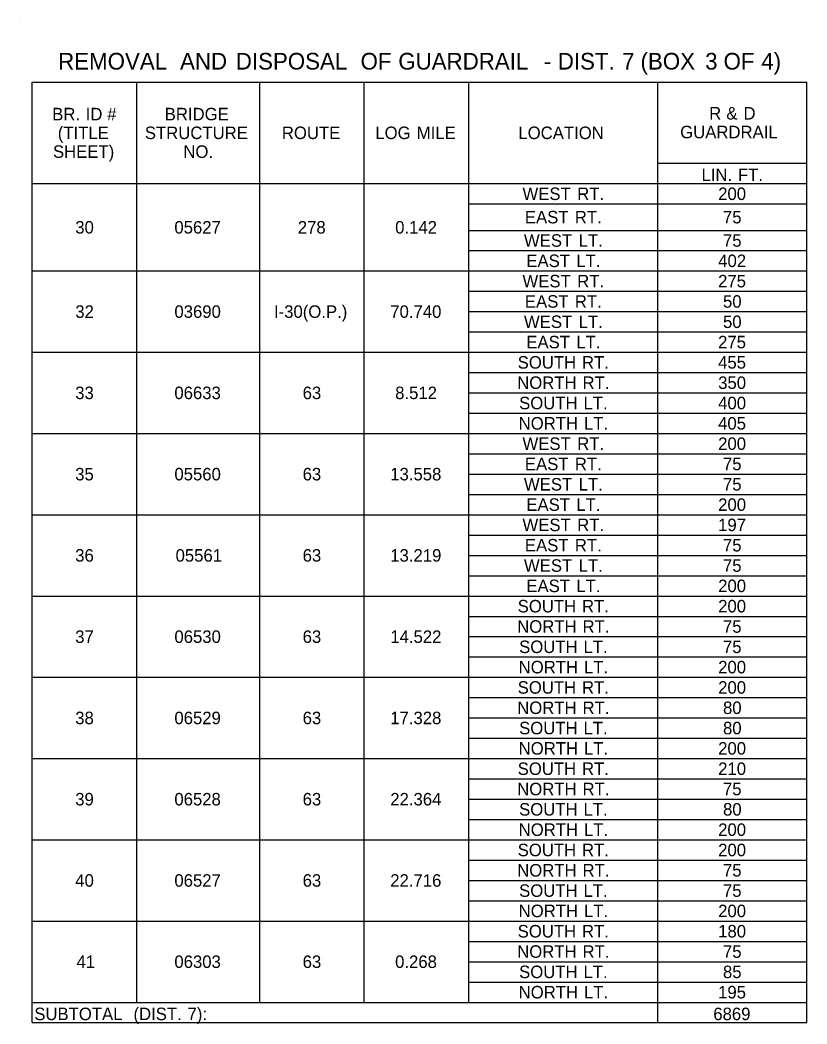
# Model space of a CAD drawing. Extents: x 544250 to 1930787, y -1948365 to 596640.
# Drawn here: x 546903.6 to 547281.5, y -1946709.2 to -1946227.5 of the extents above; entities that cross this region are included whole.
import ezdxf

# ---------------------------------------------------------------- set-up
doc = ezdxf.new("R2010")
doc.units = 0
doc.layers.add('Default', color=7, linetype='Continuous')

msp = doc.modelspace()

# ---------------------------------------------------------------- linework, layer by layer
at = {"layer": 'Default'}
for p, q in [((546903.64, -1946227.46), (546903.64, -1946227.46)), ((546909.49, -1946257.19), (547281.45, -1946257.19)), ((546909.49, -1946708.62), (546909.49, -1946257.19)), ((546909.49, -1946708.62), (546909.49, -1946257.19)), ((546959.7, -1946698.87), (546959.7, -1946257.19)), ((547018.69, -1946698.87), (547018.69, -1946257.19)), ((547068.9, -1946698.87), (547068.9, -1946257.19)), ((547119.11, -1946698.87), (547119.11, -1946257.19)), ((547209.79, -1946708.62), (547209.79, -1946257.19)), ((547281.45, -1946708.62), (547281.45, -1946257.19)), ((547281.45, -1946708.62), (547281.45, -1946257.19)), ((547209.79, -1946296.19), (547281.45, -1946296.19)), ((546909.49, -1946305.94), (547281.45, -1946305.94)), ((546909.49, -1946305.94), (547281.45, -1946305.94)), ((547119.11, -1946315.69), (547281.45, -1946315.69)), ((547119.11, -1946328.37), (547281.45, -1946328.37)), ((547119.11, -1946338.12), (547281.45, -1946338.12)), ((546909.49, -1946347.87), (547281.45, -1946347.87)), ((547119.11, -1946357.62), (547281.45, -1946357.62)), ((547119.11, -1946367.37), (547281.45, -1946367.37)), ((547119.11, -1946377.12), (547281.45, -1946377.12)), ((546909.49, -1946386.87), (547281.45, -1946386.87)), ((547119.11, -1946396.62), (547281.45, -1946396.62)), ((547119.11, -1946406.37), (547281.45, -1946406.37)), ((547119.11, -1946416.12), (547281.45, -1946416.12)), ((546909.49, -1946425.87), (547281.45, -1946425.87)), ((547119.11, -1946435.62), (547281.45, -1946435.62)), ((547119.11, -1946445.37), (547281.45, -1946445.37)), ((547119.11, -1946455.12), (547281.45, -1946455.12)), ((546909.49, -1946464.87), (547281.45, -1946464.87)), ((547119.11, -1946474.62), (547281.45, -1946474.62)), ((547119.11, -1946484.37), (547281.45, -1946484.37)), ((547119.11, -1946494.12), (547281.45, -1946494.12)), ((546909.49, -1946503.87), (547281.45, -1946503.87)), ((547119.11, -1946513.62), (547281.45, -1946513.62)), ((547119.11, -1946523.37), (547281.45, -1946523.37)), ((547119.11, -1946533.12), (547281.45, -1946533.12)), ((546909.49, -1946542.87), (547281.45, -1946542.87)), ((547119.11, -1946552.62), (547281.45, -1946552.62)), ((547119.11, -1946562.37), (547281.45, -1946562.37)), ((547119.11, -1946572.12), (547281.45, -1946572.12)), ((546909.49, -1946581.87), (547281.45, -1946581.87)), ((547119.11, -1946591.62), (547281.45, -1946591.62)), ((547119.11, -1946601.37), (547281.45, -1946601.37)), ((547119.11, -1946611.12), (547281.45, -1946611.12)), ((546909.49, -1946620.87), (547281.45, -1946620.87)), ((547119.11, -1946630.62), (547281.45, -1946630.62)), ((547119.11, -1946640.37), (547281.45, -1946640.37)), ((547119.11, -1946650.12), (547281.45, -1946650.12)), ((546909.49, -1946659.87), (547281.45, -1946659.87)), ((547119.11, -1946669.62), (547281.45, -1946669.62)), ((547119.11, -1946679.37), (547281.45, -1946679.37)), ((547119.11, -1946689.12), (547281.45, -1946689.12)), ((546909.49, -1946698.87), (547281.45, -1946698.87)), ((547209.79, -1946708.62), (547209.79, -1946698.87)), ((546909.49, -1946708.62), (547281.45, -1946708.62))]:
    msp.add_line(p, q, dxfattribs=at)

# ---------------------------------------------------------------- texts
for s, height, p in [('REMOVAL', 8, (546921.92, -1946251.2)), (' AND', 8, (546977.48, -1946251.2)), (' DISPOSAL', 8, (547004.25, -1946251.2)), (' OF', 8, (547064.16, -1946251.2)), (' GUARDRAIL', 8, (547082.27, -1946251.2)), (' DIST.', 8, (547158.85, -1946251.2)), (' 7', 8, (547189.76, -1946251.2)), (' (BOX', 8, (547198.58, -1946251.2)), (' 3', 8, (547229.62, -1946251.2)), (' OF', 8, (547238.45, -1946251.2)), (' 4)', 8, (547256.56, -1946251.2)), (' -', 8, (547152.11, -1946251.2)), ('BR.', 6, (546919.07, -1946275.57)), (' ID', 6, (546932.93, -1946275.57)), (' #', 6, (546943.23, -1946275.57)), ('BRIDGE', 6, (546973.1, -1946275.57)), ('R', 6, (547234.51, -1946275.19)), (' &', 6, (547240.52, -1946275.19)), (' D', 6, (547248.77, -1946275.19)), ('(TITLE', 6, (546921.76, -1946284.57)), ('STRUCTURE', 6, (546963.55, -1946284.57)), ('ROUTE', 6, (547029.33, -1946284.57)), ('LOG', 6, (547074.21, -1946284.57)), (' MILE', 6, (547091.87, -1946284.57)), ('LOCATION', 6, (547142.9, -1946284.57)), ('GUARDRAIL', 6, (547220.59, -1946284.19)), ('SHEET)', 6, (546919.44, -1946293.57)), ('NO.', 6, (546982.03, -1946293.57)), ('LIN.', 6, (547230.83, -1946304.74)), (' FT.', 6, (547246.09, -1946304.74)), ('WEST', 6, (547144.87, -1946313.82)), (' RT.', 6, (547168.93, -1946313.82)), ('200', 6, (547238.83, -1946313.82)), ('EAST', 6, (547146.03, -1946325.03)), (' RT.', 6, (547167.77, -1946325.03)), ('75', 6, (547241.13, -1946325.03)), ('30', 6, (546930.14, -1946329.91)), ('05627', 6, (546977.73, -1946329.91)), ('278', 6, (547036.99, -1946329.91)), ('0.142', 6, (547083.74, -1946329.91)), ('WEST', 6, (547145.57, -1946336.24)), (' LT.', 6, (547169.62, -1946336.24)), ('75', 6, (547241.13, -1946336.24)), ('EAST', 6, (547146.73, -1946345.99)), (' LT.', 6, (547168.46, -1946345.99)), ('402', 6, (547238.85, -1946345.99)), ('WEST', 6, (547144.87, -1946355.74)), (' RT.', 6, (547168.93, -1946355.74)), ('275', 6, (547238.8, -1946355.74)), ('EAST', 6, (547146.03, -1946365.49)), (' RT.', 6, (547167.77, -1946365.49)), ('50', 6, (547241.16, -1946365.49)), ('32', 6, (546930.16, -1946370.37)), ('03690', 6, (546977.74, -1946370.37)), ('I-30(O.P.)', 6, (547025.55, -1946370.37)), ('70.740', 6, (547081.39, -1946370.37)), ('WEST', 6, (547145.57, -1946375.24)), (' LT.', 6, (547169.62, -1946375.24)), ('50', 6, (547241.16, -1946375.24)), ('EAST', 6, (547146.73, -1946384.99)), (' LT.', 6, (547168.46, -1946384.99)), ('275', 6, (547238.8, -1946384.99)), ('SOUTH', 6, (547142.57, -1946394.74)), (' RT.', 6, (547171.23, -1946394.74)), ('455', 6, (547238.8, -1946394.74)), ('NORTH', 6, (547142.33, -1946404.49)), (' RT.', 6, (547171.47, -1946404.49)), ('350', 6, (547238.83, -1946404.49)), ('33', 6, (546930.12, -1946409.37)), ('06633', 6, (546977.73, -1946409.37)), ('63', 6, (547039.32, -1946409.37)), ('8.512', 6, (547083.74, -1946409.37)), ('SOUTH', 6, (547143.26, -1946414.24)), (' LT.', 6, (547171.93, -1946414.24)), ('400', 6, (547238.83, -1946414.24)), ('NORTH', 6, (547143.03, -1946423.99)), (' LT.', 6, (547172.16, -1946423.99)), ('405', 6, (547238.8, -1946423.99)), ('WEST', 6, (547144.87, -1946433.74)), (' RT.', 6, (547168.93, -1946433.74)), ('200', 6, (547238.83, -1946433.74)), ('EAST', 6, (547146.03, -1946443.49)), (' RT.', 6, (547167.77, -1946443.49)), ('75', 6, (547241.13, -1946443.49)), ('35', 6, (546930.1, -1946448.37)), ('05560', 6, (546977.74, -1946448.37)), ('63', 6, (547039.32, -1946448.37)), ('13.558', 6, (547081.38, -1946448.37)), ('WEST', 6, (547145.57, -1946453.24)), (' LT.', 6, (547169.62, -1946453.24)), ('75', 6, (547241.13, -1946453.24)), ('EAST', 6, (547146.73, -1946462.99)), (' LT.', 6, (547168.46, -1946462.99)), ('200', 6, (547238.83, -1946462.99)), ('WEST', 6, (547144.87, -1946472.74)), (' RT.', 6, (547168.93, -1946472.74)), ('197', 6, (547238.82, -1946472.74)), ('EAST', 6, (547146.03, -1946482.49)), (' RT.', 6, (547167.77, -1946482.49)), ('75', 6, (547241.13, -1946482.49)), ('36', 6, (546930.12, -1946487.37)), ('05561', 6, (546978.31, -1946487.37)), ('63', 6, (547039.32, -1946487.37)), ('13.219', 6, (547081.38, -1946487.37)), ('WEST', 6, (547145.57, -1946492.24)), (' LT.', 6, (547169.62, -1946492.24)), ('75', 6, (547241.13, -1946492.24)), ('EAST', 6, (547146.73, -1946501.99)), (' LT.', 6, (547168.46, -1946501.99)), ('200', 6, (547238.83, -1946501.99)), ('SOUTH', 6, (547142.57, -1946511.74)), (' RT.', 6, (547171.23, -1946511.74)), ('200', 6, (547238.83, -1946511.74)), ('NORTH', 6, (547142.33, -1946521.49)), (' RT.', 6, (547171.47, -1946521.49)), ('75', 6, (547241.13, -1946521.49)), ('37', 6, (546930.12, -1946526.37)), ('06530', 6, (546977.74, -1946526.37)), ('63', 6, (547039.32, -1946526.37)), ('14.522', 6, (547081.41, -1946526.37)), ('SOUTH', 6, (547143.26, -1946531.24)), (' LT.', 6, (547171.93, -1946531.24)), ('75', 6, (547241.13, -1946531.24)), ('NORTH', 6, (547143.03, -1946540.99)), (' LT.', 6, (547172.16, -1946540.99)), ('200', 6, (547238.83, -1946540.99)), ('SOUTH', 6, (547142.57, -1946550.74)), (' RT.', 6, (547171.23, -1946550.74)), ('200', 6, (547238.83, -1946550.74)), ('NORTH', 6, (547142.33, -1946560.49)), (' RT.', 6, (547171.47, -1946560.49)), ('80', 6, (547241.16, -1946560.49)), ('38', 6, (546930.12, -1946565.37)), ('06529', 6, (546977.73, -1946565.37)), ('63', 6, (547039.32, -1946565.37)), ('17.328', 6, (547081.38, -1946565.37)), ('SOUTH', 6, (547143.26, -1946570.24)), (' LT.', 6, (547171.93, -1946570.24)), ('80', 6, (547241.16, -1946570.24)), ('NORTH', 6, (547143.03, -1946579.99)), (' LT.', 6, (547172.16, -1946579.99)), ('200', 6, (547238.83, -1946579.99)), ('SOUTH', 6, (547142.57, -1946589.74)), (' RT.', 6, (547171.23, -1946589.74)), ('210', 6, (547238.83, -1946589.74)), ('NORTH', 6, (547142.33, -1946599.49)), (' RT.', 6, (547171.47, -1946599.49)), ('75', 6, (547241.13, -1946599.49)), ('39', 6, (546930.12, -1946604.37)), ('06528', 6, (546977.73, -1946604.37)), ('63', 6, (547039.32, -1946604.37)), ('22.364', 6, (547081.4, -1946604.37)), ('SOUTH', 6, (547143.26, -1946609.24)), (' LT.', 6, (547171.93, -1946609.24)), ('80', 6, (547241.16, -1946609.24)), ('NORTH', 6, (547143.03, -1946618.99)), (' LT.', 6, (547172.16, -1946618.99)), ('200', 6, (547238.83, -1946618.99)), ('SOUTH', 6, (547142.57, -1946628.74)), (' RT.', 6, (547171.23, -1946628.74)), ('200', 6, (547238.83, -1946628.74)), ('NORTH', 6, (547142.33, -1946638.49)), (' RT.', 6, (547171.47, -1946638.49)), ('75', 6, (547241.13, -1946638.49)), ('40', 6, (546930.14, -1946643.37)), ('06527', 6, (546977.73, -1946643.37)), ('63', 6, (547039.32, -1946643.37)), ('22.716', 6, (547081.38, -1946643.37)), ('SOUTH', 6, (547143.26, -1946648.24)), (' LT.', 6, (547171.93, -1946648.24)), ('75', 6, (547241.13, -1946648.24)), ('NORTH', 6, (547143.03, -1946657.99)), (' LT.', 6, (547172.16, -1946657.99)), ('200', 6, (547238.83, -1946657.99)), ('SOUTH', 6, (547142.57, -1946667.74)), (' RT.', 6, (547171.23, -1946667.74)), ('180', 6, (547238.83, -1946667.74)), ('NORTH', 6, (547142.33, -1946677.49)), (' RT.', 6, (547171.47, -1946677.49)), ('75', 6, (547241.13, -1946677.49)), ('41', 6, (546930.7, -1946682.37)), ('06303', 6, (546977.73, -1946682.37)), ('63', 6, (547039.32, -1946682.37)), ('0.268', 6, (547083.71, -1946682.37)), ('SOUTH', 6, (547143.26, -1946687.24)), (' LT.', 6, (547171.93, -1946687.24)), ('85', 6, (547241.13, -1946687.24)), ('NORTH', 6, (547143.03, -1946696.99)), (' LT.', 6, (547172.16, -1946696.99)), ('195', 6, (547238.8, -1946696.99)), ('SUBTOTAL', 6, (546910.46, -1946707.42)), (' (DIST.', 6, (546955.86, -1946707.42)), (' 7):', 6, (546981.82, -1946707.42)), ('6869', 6, (547236.49, -1946707.42))]:
    msp.add_text(s, height=height, dxfattribs=at).set_placement(p)

doc.saveas('drawing.dxf')
